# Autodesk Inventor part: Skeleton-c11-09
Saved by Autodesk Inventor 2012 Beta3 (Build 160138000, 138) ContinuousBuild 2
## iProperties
Created: 2011-01
Part Number: Skeleton-c11-09
Material: Default
Document SubType Name: Modeling
Designer: Beta-8540w
Density: 1 g/cm^3
_SkeletonDoc: Frame Skeleton File
_Version: 15.0.0
Author: Beta-8540w
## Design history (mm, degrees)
sketch "Reference Skeleton"
  geometry: L1 through (325.691, 1070.446) direction (1, 0); L2 through (404.523, 1164.395) direction (1, 0); 34 other entities
  constraints: 10 horizontal
